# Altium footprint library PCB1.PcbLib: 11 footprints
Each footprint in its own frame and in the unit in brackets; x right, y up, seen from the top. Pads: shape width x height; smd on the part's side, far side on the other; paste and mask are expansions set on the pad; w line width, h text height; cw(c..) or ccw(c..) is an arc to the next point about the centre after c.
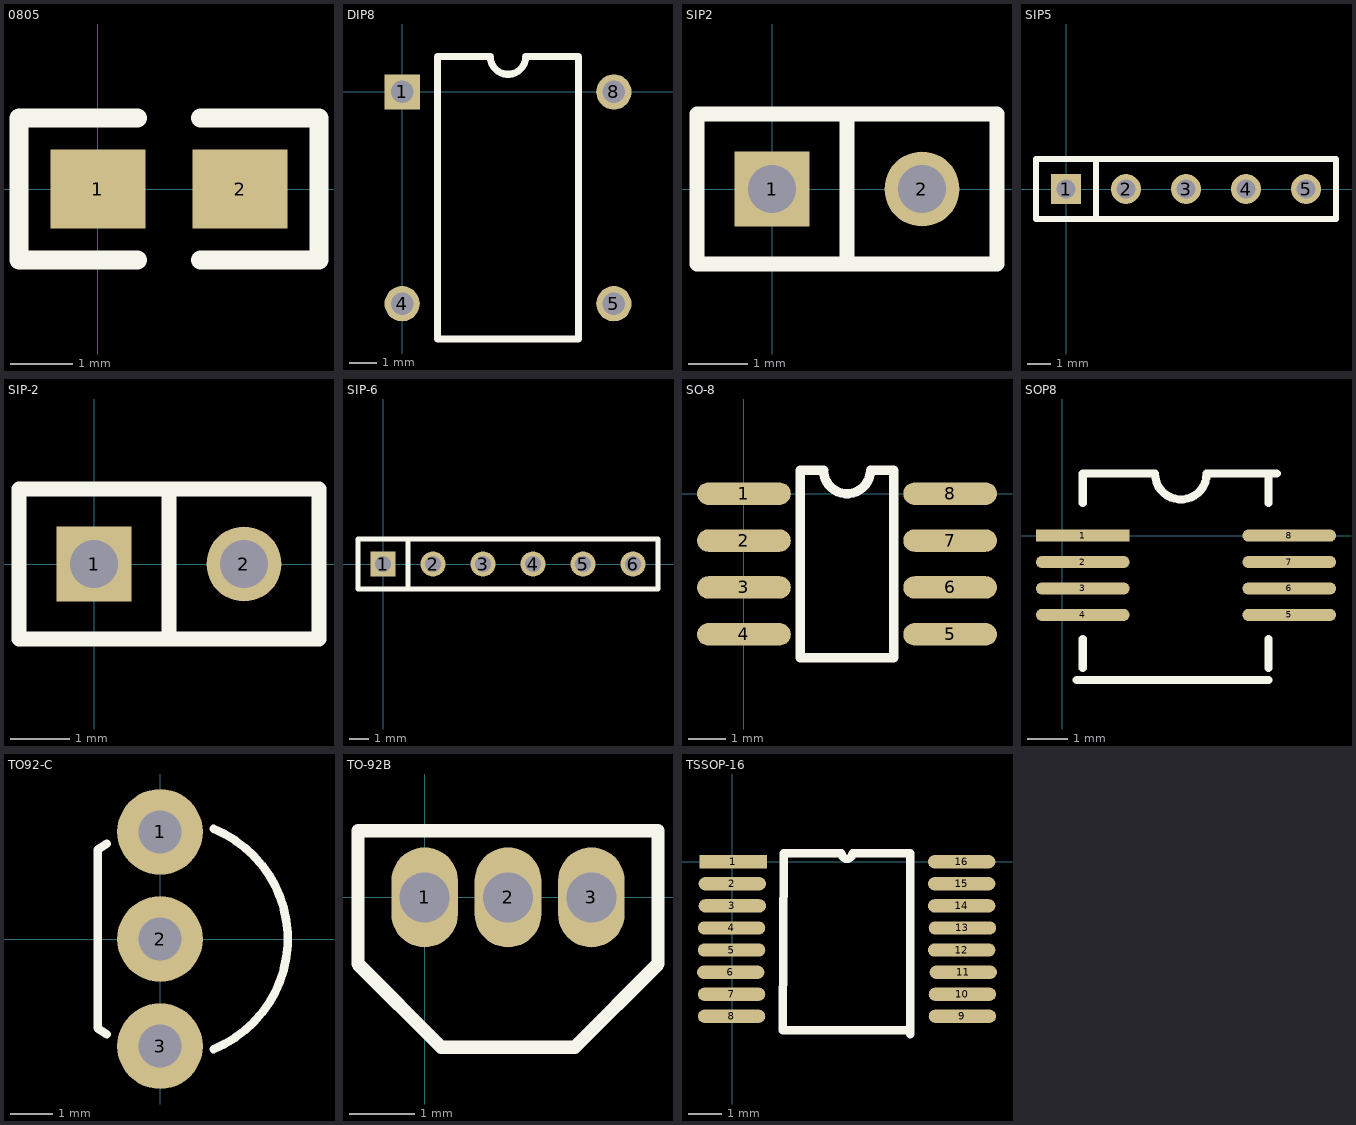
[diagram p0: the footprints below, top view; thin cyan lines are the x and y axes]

## 0805 [mil]
pads (2):
  rect 60x50 smd: 1(0,0) 2(90,0)
Top Overlay:
  lines w12: 25,-45 -50,-45 -50,45 25,45 ; 65,-45 140,-45 140,45 65,45

## DIP8 [mil]
pads (8):
  rect 50x50 hole 32: 1(0,0)
  round 0 all layers, no hole: 2(0,-100) 3(0,-200) 6(300,-200) 7(300,-100)
  round 50 hole 32: 4(0,-300) 5(300,-300) 8(300,0)
Top Overlay:
  lines w10: 50,-350 50,50 125,50 ccw(c150,50) 175,50 250,50 250,-350 50,-350

## SIP2 [mil]
pads (2):
  rect 50x50 hole 32: 1(0,0)
  round 50 hole 32: 2(100,0)
Top Overlay:
  lines w10: 50,-50 50,50 ; -50,-50 -50,50 150,50 150,-50 -50,-50

## SIP5 [mil]
pads (5):
  rect 50x50 hole 32: 1(0,0)
  round 50 hole 32: 2(100,0) 3(200,0) 4(300,0) 5(400,0)
Top Overlay:
  lines w10: 50,-50 50,50 ; -50,-50 450,-50 450,50 -50,50 -50,-50

## SIP-2 [mil]
pads (2):
  rect 50x50 hole 32: 1(0,0)
  round 50 hole 32: 2(100,0)
Top Overlay:
  lines w10: 50,-50 50,50 ; -50,-50 -50,50 150,50 150,-50 -50,-50

## SIP-6 [mil]
pads (6):
  rect 50x50 hole 32: 1(0,0)
  round 50 hole 32: 2(100,0) 3(200,0) 4(300,0) 5(400,0) 6(500,0)
Top Overlay:
  lines w10: 50,-50 50,50 ; -50,-50 -50,50 550,50 550,-50 -50,-50

## SO-8 [mil]
pads (8):
  oval 100x24 smd: 1(0,0) 2(0,-50) 3(0,-100) 4(0,-150) 5(220,-150) 6(220,-100) 7(220,-50) 8(220,0)
Top Overlay:
  lines w10: 60,-175 60,25 85,25 ccw(c110,25) 135,25 160,25 160,-175 60,-175

## SOP8 [mm]
pads (8):
  rect 2.3x0.3 smd: 1(0.508,0)
  oval 2.3x0.3 smd: 2(0.508,-0.65) 3(0.508,-1.3) 4(0.508,-1.95) 5(5.588,-1.95) 6(5.588,-1.3) 7(5.588,-0.65) 8(5.588,0)
Top Overlay:
  lines w0.2: 0.36,-3.556 5.08,-3.556 ; 0.508,-3.26 0.508,-2.54 ; 0.508,0.804 0.508,1.524 2.233,1.524 ; 2.286,1.524 ccw(c2.921,1.524) 3.556,1.524 5.281,1.524 ; 5.08,-3.26 5.08,-2.54 ; 5.08,0.804 5.08,1.524

## TO92-C [mil]
pads (3):
  round 80 hole 40: 1(0,100) 2(0,0) 3(0,-100)
Top Overlay:
  lines w7.87: -49.71,-89.08 -58.33,-83.33 -58.33,83.33 -49.71,89.08 ; 49.85,-102.76 ccw(c8.33,0) 49.85,102.76

## TO-92B [mil]
pads (3):
  oval 40x60 hole 30: 1(0,0) 2(50,0) 3(100,0)
Top Overlay:
  lines w8: -40,-40 10,-90 90,-90 140,-40 140,40 -40,40 -40,-40

## TSSOP-16 [mil]
pads (16):
  rect 80x15.75 smd: 1(1,0)
  oval 80x15.75 smd: 2(0,-26.21) 3(0,-52.42) 4(-1,-78.63) 5(-1,-104.83) 6(-2,-131.21) 7(-1,-157.25) 8(-1,-183.46) 9(273,-183.46) 10(273,-157.25) 11(274,-131.21) 12(272,-104.83) 13(273,-78.63) 14(272,-52.42) 15(272,-26.21) 16(272,0)
Top Overlay:
  lines w10: 210,-200 60,-200 61,10 129.5,10 ccw(c136,10) 142.5,10 211,10 211,-205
